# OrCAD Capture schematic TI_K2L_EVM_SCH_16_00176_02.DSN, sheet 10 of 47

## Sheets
10 PAGE37 : K2L_XDS200_1: size C; title: XDS200 / AM1802, flash, USB connector for Emulator
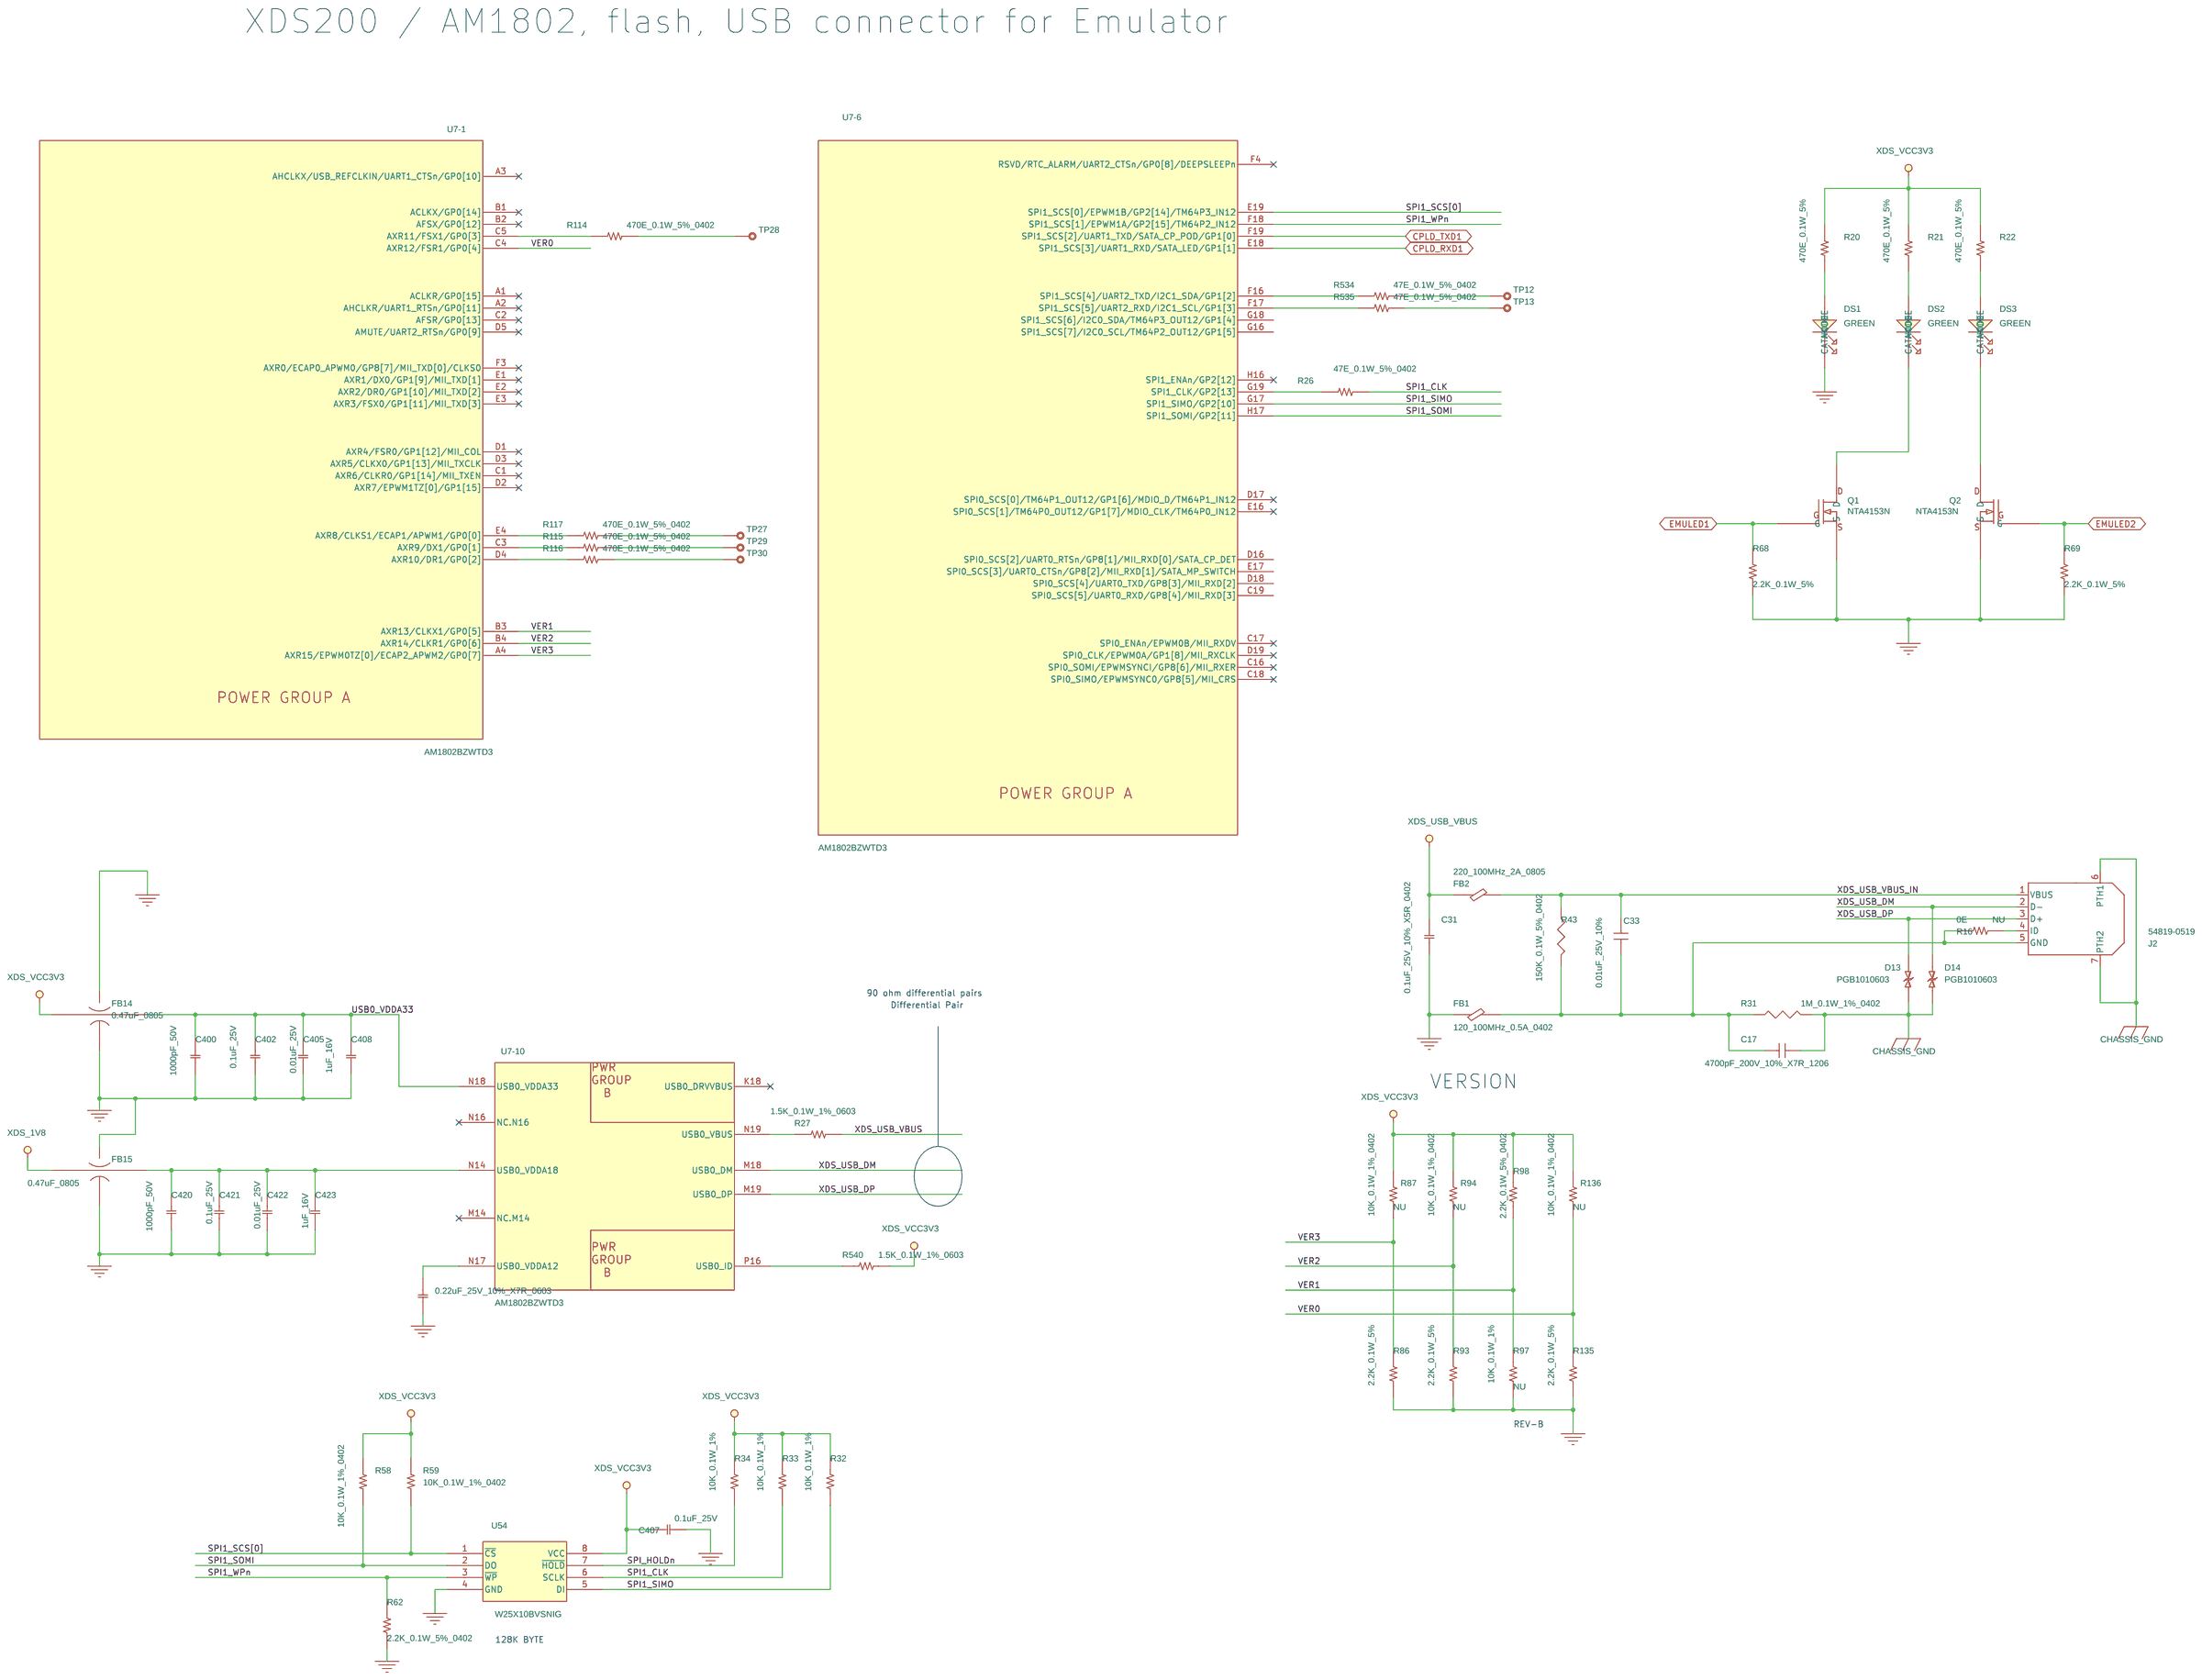
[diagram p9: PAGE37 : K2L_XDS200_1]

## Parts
sheet PAGE37 : K2L_XDS200_1
C17  4700pF_200V_10%_X7R_1206  [C1206-40X70]
C31  0.1uF_25V_10%_X5R_0402  [C0402]
C33  0.01uF_25V_10%  [C0402]
C400  1000pF_50V  [C0402]
C402  0.1uF_25V  [C0402]
C405  0.01uF_25V  [C0402]
C407  0.1uF_25V  [C0402]
C408  1uF_16V  [C0402]
C409  0.22uF_25V_10%_X7R_0603  [C0603]
C420  1000pF_50V  [C0402]
C421  0.1uF_25V  [C0402]
C422  0.01uF_25V  [C0402]
C423  1uF_16V  [C0402]
D13  PGB1010603  [SUP_PGB1010603MR]
D14  PGB1010603  [SUP_PGB1010603MR]
DS1  GREEN  [led603-35x45-rev]
DS2  GREEN  [led603-35x45-rev]
DS3  GREEN  [led603-35x45-rev]
FB1  120_100MHz_0.5A_0402  [L0402]
FB2  220_100MHz_2A_0805  [L0805]
FB14  0.47uF_0805  [FIL_NFM21PC]
FB15  0.47uF_0805  [FIL_NFM21PC]
J2  54819-0519  [MOL54819-0519]
Q1  NTA4153N  [SOT416_3P]
Q2  NTA4153N  [SOT416_3P]
R16  0E  [R0402]
R20  470E_0.1W_5%  [R0402]
R21  470E_0.1W_5%  [R0402]
R22  470E_0.1W_5%  [R0402]
R26  47E_0.1W_5%_0402  [R0402]
R27  1.5K_0.1W_1%_0603  [R0603]
R31  1M_0.1W_1%_0402  [R0402]
R32  10K_0.1W_1%  [R0402]
R33  10K_0.1W_1%  [R0402]
R34  10K_0.1W_1%  [R0402]
R43  150K_0.1W_5%_0402  [R0402]
R58  10K_0.1W_1%_0402  [R0402]
R59  10K_0.1W_1%_0402  [R0402]
R62  2.2K_0.1W_5%_0402  [R0402]
R68  2.2K_0.1W_5%  [R0402]
R69  2.2K_0.1W_5%  [R0402]
R86  2.2K_0.1W_5%  [R0402]
R87  10K_0.1W_1%_0402  [R0402]
R93  2.2K_0.1W_5%  [R0402]
R94  10K_0.1W_1%_0402  [R0402]
R97  10K_0.1W_1%  [R0402]
R98  2.2K_0.1W_5%_0402  [R0402]
R114  470E_0.1W_5%_0402  [R0402]
R115  470E_0.1W_5%_0402  [R0402]
R116  470E_0.1W_5%_0402  [R0402]
R117  470E_0.1W_5%_0402  [R0402]
R135  2.2K_0.1W_5%  [R0402]
R136  10K_0.1W_1%_0402  [R0402]
R534  47E_0.1W_5%_0402  [R0402]
R535  47E_0.1W_5%_0402  [R0402]
R540  1.5K_0.1W_1%_0603  [R0603]
TP12  Test Point  [TP-S40]
TP13  Test Point  [TP-S40]
TP27  TP  [TP-S40]
TP28  TP  [TP-S40]
TP29  TP  [TP-S40]
TP30  TP  [TP-S40]
U54  W25X10BVSNIG  [SOIC127P600_8]
sheet PAGE39 : K2L_XDS200_3
U7  AM1802BZWTD3  [BGA80P_16X16_361]  (sections -1,-10,-11,-12,-13,-14,-15,-16,-2,-3,-4,-5,-6,-7,-8,-9)

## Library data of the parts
C17 = Cap_100nF_Cermc_16V_10%_603_6: CAP CER 4700PF 200V 10% X7R 1206; Distributor_name: DIGIKEY; Distributor_part_number: 399-8198-1-ND; Manufacture: Kemet; Manufacture Part Number: C1206C472K2RACTU; Manufacture(English): Kemet; Manufacture_Part_Number: ECJ-1VB1C104K; Manufacturer: Kemet; Manufacturer_Part_No: C1206C472K2RACTU; Mfr_name: Kemet; Mfr_part_number: C1206C472K2RACTU; Part #: 103604-1472R; Vendor: DIGIKEY; Vendor_Part_No: 399-8198-1-ND
C31 C407 = 11_C_0: CAP CER 0.1UF 25V 10% X5R 0402; Alt Mfg: Taiyo Yuden; Distributor_name: DIGIKEY; Distributor_part_number: 445-4964-1-ND; EIC Part#: 03_00470_02; Manufacture: TDK Corporation; Manufacture Part Number: C1005X5R1E104K050BC; Manufacture(English): TDK Corporation; Manufacture_Part_Number: GRM155R61E104KA87D; Manufacturer: TDK Corporation; Manufacturer_Part_No: C1005X5R1E104K050BC; Mfg: Murata Electronics North America; Mfg Part#: 03_00470_02; Mfr_name: TDK Corporation; Mfr_part_number: C1005X5R1E104K050BC; Oper. Temp. Range: -55°C ~ 85°C; Package: 0402; Price @ 1: 0.10000; Price @ 1K: 0.00960; ProcessType: SMT; RoHS: Yes; Tolerance: 10%; Vendor: DIGIKEY; Vendor Part#: 445-4964-1-ND; Vendor_Part_No: 445-4964-1-ND; eI Part#: 03_00470_02
C33 = Cap_100nF_Cermc_16V_10%_603_6: CAP CER 10000PF 25V 10% X7R 0402; Distributor_name: DIGIKEY; Distributor_part_number: 445-1260-1-ND; EIC Part#: 03_00029_04; Manufacture: TDK Corporation; Manufacture Part Number: C1005X7R1E103K; Manufacture(English): TDK Corporation; Manufacture_Part_Number: C1005X7R1E103K; Manufacturer: TDK Corporation; Manufacturer_Part_No: C1005X7R1E103K; Mfg: TDK Corporation; Mfg Part#: 03_00455_02; Mfr_name: TDK Corporation; Mfr_part_number: C1005X7R1E103K; Price @ 1: 0.10000; Price @ 10K: 0.00460; Price @ 1K: 0.00600; ProcessType: SMT; Vendor: DIGIKEY; Vendor_Part_No: 445-1260-1-ND; eI Part#: 03_00029_04
C400 C420 = 11_C_0: CAP CER 1000PF 50V 10% X7R 0402; Advansus_Part_Number: 11G232110214030; Distributor_name: DIGIKEY; Distributor_part_number: 1276-1493-1-ND; EIC Part#: 03_00591_01; Manufacture: Samsung; Manufacture Part Number: CL05B102KB5NFNC; Manufacture(English): Samsung; Manufacture_Part_Number: CL05B102KB5NFNC; Manufacturer: Samsung; Manufacturer_Part_No: CL05B102KB5NFNC; Mfg: Samsung; Mfg Part#: CL05B102KB5NFNC; Mfr_name: Samsung; Mfr_part_number: CL05B102KB5NFNC; Oper. Temp. Range: -55C to 85C; Package: 0402; Price @ 1: 0.10000; Price @ 10K: 0.00260; Price @ 1K: 0.00372; ProcessType: SMT; RoHS: Yes; Tolerance: 10%; Vendor: DIGIKEY; Vendor Part#: 1276-1493-1-ND; Vendor_Part_No: 1276-1493-1-ND; Voltage: 50V; eI Part#: 03_00591_01
C402 C421 = 11_C_12: CAP CER 0.1UF 25V 10% X5R 0402; Alt Mfg: Taiyo Yuden; Distributor_name: DIGIKEY; Distributor_part_number: 445-4964-1-ND; EIC Part#: 03_00470_02; Manufacture: TDK Corporation; Manufacture Part Number: C1005X5R1E104K050BC; Manufacture(English): TDK Corporation; Manufacture_Part_Number: GRM155R61E104KA87D; Manufacturer: TDK Corporation; Manufacturer_Part_No: C1005X5R1E104K050BC; Mfg: Murata Electronics North America; Mfg Part#: 03_00470_02; Mfr_name: TDK Corporation; Mfr_part_number: C1005X5R1E104K050BC; Oper. Temp. Range: -55°C ~ 85°C; Package: 0402; Price @ 1: 0.10000; Price @ 1K: 0.00960; ProcessType: SMT; RoHS: Yes; Tolerance: 10%; Vendor: DIGIKEY; Vendor Part#: 445-4964-1-ND; Vendor_Part_No: 445-4964-1-ND; eI Part#: 03_00470_02
C405 C422 = 11_C_0: CAP CER 10000PF 25V 10% X7R 0402; Alt Mfg: Murata; Alt Mfg Part#: GRM155R71C103KA01D; Distributor_name: DIGIKEY; Distributor_part_number: 445-1260-1-ND; EIC Part#: 03_00029_04; Manufacture: TDK Corporation; Manufacture Part Number: C1005X7R1E103K; Manufacture(English): TDK Corporation; Manufacture_Part_Number: C1005X7R1E103K; Manufacturer: TDK Corporation; Manufacturer_Part_No: C1005X7R1E103K; Mfg: TDK Corporation; Mfg Part#: 03_00029_04; Mfr_name: TDK Corporation; Mfr_part_number: C1005X7R1E103K; Oper. Temp. Range: -55C to 125C; Package: 0402; Price @ 1: 0.10000; Price @ 10K: 0.00420; Price @ 1K: 0.00600; ProcessType: SMT; RoHS: Yes; Tolerance: 10%; Vendor: DIGIKEY; Vendor Part#: PCC103BQCT-ND; Vendor_Part_No: 445-1260-1-ND; Voltage: 16V; eI Part#: 03_00029_04
C408 C423 = 11_C_12: CAP CER 1UF 16V 10% X5R 0402; Characteristic: <Characteristic>; Distributor_name: DIGIKEY; Distributor_part_number: 445-4978-1-ND; EIC Part#: 03_00355_04; Manufacture: TDK Corporation; Manufacture Part Number: C1005X5R1C105K050BC; Manufacture(English): TDK Corporation; Manufacture_Part_Number: C1005X5R1C105K050BC; Manufacturer: TDK Corporation; Manufacturer_Part_No: C1005X5R1C105K050BC; Mfg: TDK Corporation; Mfg Part#: C1005X5R1C105K050BC; Mfr_name: TDK Corporation; Mfr_part_number: C1005X5R1C105K050BC; Oper. Temp. Range: -55C to 85C; Package: 0402; Price @ 1: 0.12000; Price @ 10K: 0.01600; Price @ 1K: 0.02200; ProcessType: SMT; RoHS: Yes; Tolerance: 10%; Vendor: DIGIKEY; Vendor Part#: 445-4978-1-ND; Vendor_Part_No: 445-4978-1-ND; Voltage: 6.3V; eI Part#: 03_00355_04
C409 = 11_C_0: CAP CER 0.22UF 25V 10% X7R 0603; Distributor_name: DIGIKEY; Distributor_part_number: 490-3290-1-ND; EIC Part#: TBD; Manufacture: Murata; Manufacture Part Number: GRM188R71E224KA88D; Manufacture(English): Murata; Manufacture_Part_Number: GRM188R71E224KA88D; Manufacturer: Murata; Manufacturer_Part_No: GRM188R71E224KA88D; Mfg Part#: TBD; Mfr_name: Murata; Mfr_part_number: GRM188R71E224KA88D; Oper. Temp. Range: -55C ~ 125C; Package: 0603; ProcessType: SMT; RoHS: Yes; Tolerance: 10%; Vendor: DIGIKEY; Vendor Part#: 490-3290-1-ND; Vendor_Part_No: 490-3290-1-ND; eI Part#: TBD
D13 D14 = 130_ESD_D0603_0: SUPPRESSOR ESD 24VDC 0603 SMD; Distributor_name: DIGIKEY; Distributor_part_number: F2594CT-ND; EIC Part#: TBD; Manufacture: Littelfuse Inc; Manufacture Part Number: PGB1010603MR; Manufacture(English): Littelfuse Inc; Manufacture_Part_Number: PGB1010603MR; Manufacturer: Littelfuse Inc; Manufacturer_Part_No: PGB1010603MR; Mfg Part#: TBD; Mfr_name: Littelfuse Inc; Mfr_part_number: PGB1010603MR; Package: 0603; ProcessType: SMT; RoHS: Yes; Vendor: DIGIKEY; Vendor Part#: F2594CT-ND; Vendor_Part_No: F2594CT-ND; eI Part#: TBD
DS1-DS3 = SMF-2432GC_1: LED 570NM GRN WHT/DIFF 0603 SMD; Distributor_name: DIGIKEY; Distributor_part_number: 511-1308-1-ND; EIC Part#: 06_00364_01; Manufacture: Rohm Semiconductor; Manufacture Part Number: SML-510MWT86; Manufacture(English): Rohm Semiconductor; Manufacturer: Rohm Semiconductor; Manufacturer_Part_No: SML-510MWT86; Mfg Part#: 06_00364_01; Mfr_name: Rohm Semiconductor; Mfr_part_number: SML-510MWT86; Part #: 103557-0001R; Vendor: DIGIKEY; Vendor_Part_No: 511-1308-1-ND; eI Part#: 06_00364_01
FB1 = 1212_BEAD_0: FERRITE CHIP 120 OHM 500MA 0402; Distributor_name: DIGIKEY; Distributor_part_number: 490-1005-1-ND; EIC Part#: 04_00075_01; Manufacture: Murata; Manufacture Part Number: BLM15AG121SN1D; Manufacture(English): Murata; Manufacture_Part_Number: BLM15AG121SN1D; Manufacturer: Murata; Manufacturer_Part_No: BLM15AG121SN1D; Mfg: Murata Electronics North America; Mfg Part#: BLM15AG121SN1D; Mfr_name: Murata; Mfr_part_number: BLM15AG121SN1D; Oper. Temp. Range: -55C to 85C; Package: 0402; Price @ 1: 0.10000; Price @ 10K: 0.02016; Price @ 1K: 0.02905; ProcessType: SMT; RoHS: Yes; Tolerance: 25%; Vendor: DIGIKEY; Vendor Part#: 490-1005-1-ND; Vendor_Part_No: 490-1005-1-ND; eI Part#: 04_00075_01
FB2 = 1212_BEAD_0: FERRITE CHIP 220 OHM 0805; Distributor_name: DIGIKEY; Distributor_part_number: 490-1054-1-ND; EIC Part#: 04_00016_01; Manufacture: Murata; Manufacture Part Number: BLM21PG221SN1D; Manufacture(English): Murata; Manufacture_Part_Number: BLM21PG221SN1D; Manufacturer: Murata; Manufacturer_Part_No: BLM21PG221SN1D; Mfg: Murata Electronics North America; Mfg Part#: 04_00016_01; Mfr_name: Murata; Mfr_part_number: BLM21PG221SN1D; Oper. Temp. Range: -55C to 85C; Package: 0805; Price @ 1: 0.11000; Price @ 10K: 0.02368; Price @ 1K: 0.03093; ProcessType: SMT; RoHS: Yes; Vendor: DIGIKEY; Vendor Part#: 490-1054-1-ND; Vendor_Part_No: 490-1054-1-ND; eI Part#: 04_00016_01
FB14 FB15 = NFM_3: FILTER LC HIGH FREQ .47UF 0805; Distributor_name: DIGIKEY; Distributor_part_number: 490-2537-1-ND; EIC Part#: 04_00213_01; Manufacture: Murata; Manufacture Part Number: NFM21PC474R1C3D; Manufacture(English): Murata; Manufacture_Part_Number: NFM21PC474R1C3D; Manufacturer: Murata; Manufacturer_Part_No: NFM21PC474R1C3D; Mfg Part#: 04_00213_01; Mfr_name: Murata; Mfr_part_number: NFM21PC474R1C3D; Part #: 102569-1470R; RoHS: Yes; Tolerance: 20%; Vendor: DIGIKEY; Vendor Part#: 490-2537-1-ND; Vendor_Part_No: 490-2537-1-ND; eI Part#: 04_00213_01
J2 = 678038020_0: MINI USB TYPE B CONNECTOR, RCPT 5POS THD; Distributor_name: ELEMENT14; Distributor_part_number: 2133828; EIC Part#: 09_00954_01; Manufacture: Molex Inc; Manufacture(English): Molex Inc; Manufacturer: Molex Inc; Mfg: Molex Inc; Mfg Part#: 09_00954_01; Mfr_name: Molex Inc; Price @ 1: 2.40000; Price @ 10K: 1.77000; Price @ 1K: 1.77000; Vendor: ELEMENT14; Vendor_Part_No: 2133828; eI Part#: 09_00954_01
Q1 Q2 = NTA4153N: MOSFET N-CH 20V 915MA SOT-416; Distributor_name: DIGIKEY; Distributor_part_number: NTA4153NT1GOSCT-ND; EIC Part#: 07_00042_01; Manufacture: ON Semiconductor; Manufacture Part Number: NTA4153NT1G; Manufacture(English): ON Semiconductor; Manufacture_Part_Number: NTA4153NT1G; Manufacturer: ON Semiconductor; Manufacturer_Part_No: NTA4153NT1G; Mfg Part#: 07_00042_01; Mfr_name: ON Semiconductor; Mfr_part_number: NTA4153NT1G; Package: SC-75; Part #: 102437-0001R; RoHS: Yes; Vendor: DIGIKEY; Vendor Part#: NTA4153NT1GOSCT-ND; Vendor_Part_No: NTA4153NT1GOSCT-ND; eI Part#: 07_00042_01
R16 = 10_R_0: RES 0.0 OHM 1/10W JUMP 0402 SMD; Alt Mfg: Yageo; Distributor_name: DIGIKEY; Distributor_part_number: P0.0JCT-ND; EIC Part#: 02_00019_01; Manufacture: Panasonic - ECG; Manufacture Part Number: ERJ-2GE0R00X; Manufacture(English): Panasonic - ECG; Manufacture_Part_Number: ERJ-2GE0R00X; Manufacturer: Panasonic - ECG; Manufacturer_Part_No: ERJ-2GE0R00X; Mfg: Panasonic - ECG; Mfg Part#: 02_00019_01; Mfr_name: Panasonic - ECG; Mfr_part_number: ERJ-2GE0R00X; Mounting Status: NU; Oper. Temp. Range: -55C to 125C; Package: 0402; ProcessType: SMT; Remark: Alt part is 1/16W; RoHS: Yes; Tolerance: 5%; Vendor: DIGIKEY; Vendor Part#: P0.0JCT-ND; Vendor_Part_No: P0.0JCT-ND; eI Part#: 02_00019_01
R20-R22 R116 = 10_R_0: RES 470 OHM 1/10W 5% 0402 SMD; Alt Mfg: Yageo; Alt Mfg Part#: RC0402JR-070RL; Distributor_name: DIGIKEY; Distributor_part_number: P470JCT-ND; EIC Part#: 02_00483_01; Manufacture: Panasonic - ECG; Manufacture Part Number: ERJ-2GEJ471X; Manufacture(English): Panasonic - ECG; Manufacture_Part_Number: ERJ-2GEJ471X; Manufacturer: Panasonic - ECG; Manufacturer_Part_No: ERJ-2GEJ471X; Mfg Part#: 02_00483_01; Mfr_name: Panasonic - ECG; Mfr_part_number: ERJ-2GEJ471X; Oper. Temp. Range: -55C to 125C; Package: 0402; ProcessType: SMT; Remark: Alt part is 1/16W; RoHS: Yes; Tolerance: 5%; Vendor: DIGIKEY; Vendor Part#: P470JDKR-ND; Vendor_Part_No: P470JCT-ND; eI Part#: 02_00045_01
R26 R535 = 10_R_0: RES 47 OHM 1/10W 5% 0402 SMD; Alt Mfg: Yageo; Alt Mfg Part#: RC0402JR-070RL; Distributor_name: DIGIKEY; Distributor_part_number: P47JCT-ND; EIC Part#: 02_00558_01; Manufacture: Panasonic - ECG; Manufacture Part Number: ERJ-2GEJ470X; Manufacture(English): Panasonic - ECG; Manufacture_Part_Number: ERJ-2GEJ470X; Manufacturer: Panasonic - ECG; Manufacturer_Part_No: ERJ-2GEJ470X; Mfg Part#: 02_00558_01; Mfr_name: Panasonic - ECG; Mfr_part_number: ERJ-2GEJ470X; Oper. Temp. Range: -55C to 125C; Package: 0402; ProcessType: SMT; Remark: Alt part is 1/16W; RoHS: Yes; Tolerance: 5%; Vendor: DIGIKEY; Vendor Part#: P47JCT-ND; Vendor_Part_No: P47JCT-ND; eI Part#: 02_00027_01
R27 R540 = 10_R_0: RES 1.50K OHM 1/10W 1% 0603 SMD; Distributor_name: DIGIKEY; Distributor_part_number: P1.50KHCT-ND; EIC Part#: 02_00122_02; Manufacture: Panasonic - ECG; Manufacture Part Number: ERJ-3EKF1501V; Manufacture(English): Panasonic - ECG; Manufacture_Part_Number: ERJ-3EKF1501V; Manufacturer: Panasonic - ECG; Manufacturer_Part_No: ERJ-3EKF1501V; Mfg Part#: 02_00122_02; Mfr_name: Panasonic - ECG; Mfr_part_number: ERJ-3EKF1501V; Oper. Temp. Range: -55C to 125C; Package: 0603; ProcessType: SMT; RoHS: Yes; Tolerance: 1%; Vendor: DIGIKEY; Vendor Part#: P1.50KHCT-ND; Vendor_Part_No: P1.50KHCT-ND; eI Part#: 02_00027_01
R31 = R: RES 1.00M OHM 1/16W 1% 0402 SMD; Distributor_name: DIGIKEY; Distributor_part_number: 311-1.00MLRCT-ND; EIC Part#: 02_00057_02; Manufacture: Yageo; Manufacture Part Number: RC0402FR-071ML; Manufacture(English): Yageo; Manufacturer: Yageo; Manufacturer_Part_No: RC0402FR-071ML; Mfg Part#: 02_00095_01; Mfr_name: Yageo; Mfr_part_number: RC0402FR-071ML; Vendor: DIGIKEY; Vendor_Part_No: 311-1.00MLRCT-ND; eI Part#: 02_00057_02
R32-R34 R58 R59 = 10_R_0: RES 10K OHM 1/10W 1% 0402 SMD; Alt Mfg: Yageo; Alt Mfg Part#: RC0402FR-0710KL; Distributor_name: DIGIKEY; Distributor_part_number: P10.0KLCT-ND; EIC Part#: 02_00027_01; Manufacture: Panasonic - ECG; Manufacture Part Number: ERJ-2RKF1002X; Manufacture(English): Panasonic - ECG; Manufacture_Part_Number: ERJ-2RKF1002X; Manufacturer: Panasonic - ECG; Manufacturer_Part_No: ERJ-2RKF1002X; Mfg Part#: 02_00027_01; Mfr_name: Panasonic - ECG; Mfr_part_number: ERJ-2RKF1002X; Oper. Temp. Range: -55C ~ 125C; Package: 0402; Price @ 1: 0.10000; Price @ 10K: 0.00347; Price @ 1K: 0.00672; ProcessType: SMT; Remark: Alt part is 1/16W; RoHS: Yes; Tolerance: 1%; Vendor: DIGIKEY; Vendor Part#: P10.0KLCT-ND; Vendor_Part_No: P10.0KLCT-ND; eI Part#: 02_00027_01
R43 = R: RES 150K OHM 1/10W 5% 0402 SMD; Distributor_name: DIGIKEY; Distributor_part_number: P150KJCT-ND; EIC Part#: 02_00366_02; Manufacture: Panasonic - ECG; Manufacture Part Number: ERJ-2GEJ154X; Manufacture(English): Panasonic - ECG; Manufacturer: Panasonic - ECG; Manufacturer_Part_No: ERJ-2GEJ154X; Mfg Part#: 02_00366_02; Mfr_name: Panasonic - ECG; Mfr_part_number: ERJ-2GEJ154X; Part #: 101370-1504R; Part Number: ECJ-1VB1C104K; Type: X7R Ceramic Chip Cap; Vendor: DIGIKEY; Vendor_Part_No: P150KJCT-ND; eI Part#: 02_00045_01
R62 = 10_R_0: RES 2.2K OHM 1/10W 5% 0402 SMD; Alt Mfg: Yageo; Alt Mfg Part#: RC0402JR-072K2L; Distributor_name: DIGIKEY; Distributor_part_number: P2.2KJCT-ND; EIC Part#: 02_00024_01; Manufacture: Panasonic - ECG; Manufacture Part Number: ERJ-2GEJ222X; Manufacture(English): Panasonic - ECG; Manufacture_Part_Number: ERJ-2GEJ222X; Manufacturer: Panasonic - ECG; Manufacturer_Part_No: ERJ-2GEJ222X; Mfg Part#: 02_00024_01; Mfr_name: Panasonic - ECG; Mfr_part_number: ERJ-2GEJ222X; Oper. Temp. Range: -55C to 125C; Package: 0402; ProcessType: SMT; Remark: Alt part is 1/16W; RoHS: Yes; Specifications: RES 2.2K OHM 1/10W 5% 0402 SMD; Tolerance: 5%; Vendor: DIGIKEY; Vendor Part#: P2.2KJCT-ND; Vendor_Part_No: P2.2KJCT-ND; eI Part#: 02_00233_01
R68 R69 R135 = 10_R_0: RES 2.2K OHM 1/10W 5% 0402 SMD; Alt Mfg: Yageo; Alt Mfg Part#: RC0402JR-072K2L; Distributor_name: DIGIKEY; Distributor_part_number: P2.2KJCT-ND; EIC Part#: 02_00024_01; Manufacture: Panasonic - ECG; Manufacture Part Number: ERJ-2GEJ222X; Manufacture(English): Panasonic - ECG; Manufacture_Part_Number: ERJ-2GEJ222X; Manufacturer: Panasonic - ECG; Manufacturer_Part_No: ERJ-2GEJ222X; Mfg Part#: 02_00024_01; Mfr_name: Panasonic - ECG; Mfr_part_number: ERJ-2GEJ222X; Oper. Temp. Range: -55C to 125C; Package: 0402; ProcessType: SMT; Remark: Alt part is 1/16W; RoHS: Yes; Specifications: RES 2.2K OHM 1/10W 5% 0402 SMD; Tolerance: 5%; Vendor: DIGIKEY; Vendor Part#: P2.2KJCT-ND; Vendor_Part_No: P2.2KJCT-ND; eI Part#: 02_00045_01
R86 R93 = 10_R_0: RES 2.2K OHM 1/10W 5% 0402 SMD; Alt Mfg: Yageo; Alt Mfg Part#: RC0402JR-072K2L; Distributor_name: DIGIKEY; Distributor_part_number: P2.2KJCT-ND; EIC Part#: 02_00024_01; Manufacture: Panasonic - ECG; Manufacture Part Number: ERJ-2GEJ222X; Manufacture(English): Panasonic - ECG; Manufacture_Part_Number: ERJ-2GEJ222X; Manufacturer: Panasonic - ECG; Manufacturer_Part_No: ERJ-2GEJ222X; Mfg Part#: 02_00024_01; Mfr_name: Panasonic - ECG; Mfr_part_number: ERJ-2GEJ222X; Oper. Temp. Range: -55C to 125C; Package: 0402; ProcessType: SMT; Remark: Alt part is 1/16W; RoHS: Yes; Specifications: RES 2.2K OHM 1/10W 5% 0402 SMD; Tolerance: 5%; Vendor: DIGIKEY; Vendor Part#: P2.2KJCT-ND; Vendor_Part_No: P2.2KJCT-ND; eI Part#: 02_00027_01
R87 R94 R97 R136 = 10_R_0: RES 10K OHM 1/10W 1% 0402 SMD; Alt Mfg: Yageo; Alt Mfg Part#: RC0402FR-0710KL; Distributor_name: DIGIKEY; Distributor_part_number: P10.0KLCT-ND; EIC Part#: 02_00027_01; Manufacture: Panasonic - ECG; Manufacture Part Number: ERJ-2RKF1002X; Manufacture(English): Panasonic - ECG; Manufacture_Part_Number: ERJ-2RKF1002X; Manufacturer: Panasonic - ECG; Manufacturer_Part_No: ERJ-2RKF1002X; Mfg Part#: 02_00027_01; Mfr_name: Panasonic - ECG; Mfr_part_number: ERJ-2RKF1002X; Mounting: NU; Mounting Status: NU; Mounting_Status: NU; Oper. Temp. Range: -55C ~ 125C; Package: 0402; Price @ 1: 0.10000; Price @ 10K: 0.00347; Price @ 1K: 0.00672; ProcessType: SMT; Remark: Alt part is 1/16W; RoHS: Yes; Tolerance: 1%; Vendor: DIGIKEY; Vendor Part#: P10.0KLCT-ND; Vendor_Part_No: P10.0KLCT-ND; eI Part#: 02_00027_01
R98 = 10_R_0: RES 2.2K OHM 1/10W 5% 0402 SMD; Alt Mfg: Yageo; Alt Mfg Part#: RC0402JR-072K2L; Distributor_name: DIGIKEY; Distributor_part_number: P2.2KJCT-ND; EIC Part#: 02_00024_01; Manufacture: Panasonic - ECG; Manufacture Part Number: ERJ-2GEJ222X; Manufacture(English): Panasonic - ECG; Manufacture_Part_Number: ERJ-2GEJ222X; Manufacturer: Panasonic - ECG; Manufacturer_Part_No: ERJ-2GEJ222X; Mfg Part#: 02_00024_01; Mfr_name: Panasonic - ECG; Mfr_part_number: ERJ-2GEJ222X; Oper. Temp. Range: -55C to 125C; Package: 0402; ProcessType: SMT; Remark: Alt part is 1/16W; RoHS: Yes; Specifications: RES 2.2K OHM 1/10W 5% 0402 SMD; Tolerance: 5%; Vendor: DIGIKEY; Vendor Part#: P2.2KJCT-ND; Vendor_Part_No: P2.2KJCT-ND; eI Part#: 02_00483_01
R114 = 10_R_0: RES 470 OHM 1/10W 5% 0402 SMD; Alt Mfg: Yageo; Alt Mfg Part#: RC0402JR-070RL; Distributor_name: DIGIKEY; Distributor_part_number: P470JCT-ND; EIC Part#: 02_00483_01; Manufacture: Panasonic - ECG; Manufacture Part Number: ERJ-2GEJ471X; Manufacture(English): Panasonic - ECG; Manufacture_Part_Number: ERJ-2GEJ471X; Manufacturer: Panasonic - ECG; Manufacturer_Part_No: ERJ-2GEJ471X; Mfg Part#: 02_00483_01; Mfr_name: Panasonic - ECG; Mfr_part_number: ERJ-2GEJ471X; Oper. Temp. Range: -55C to 125C; Package: 0402; ProcessType: SMT; Remark: Alt part is 1/16W; RoHS: Yes; Tolerance: 5%; Vendor: DIGIKEY; Vendor Part#: P470JDKR-ND; Vendor_Part_No: P470JCT-ND; eI Part#: 02_00483_01
R115 R117 = 10_R_0: RES 470 OHM 1/10W 5% 0402 SMD; Alt Mfg: Yageo; Alt Mfg Part#: RC0402JR-070RL; Distributor_name: DIGIKEY; Distributor_part_number: P470JCT-ND; EIC Part#: 02_00483_01; Manufacture: Panasonic - ECG; Manufacture Part Number: ERJ-2GEJ471X; Manufacture(English): Panasonic - ECG; Manufacture_Part_Number: ERJ-2GEJ471X; Manufacturer: Panasonic - ECG; Manufacturer_Part_No: ERJ-2GEJ471X; Mfg Part#: 02_00483_01; Mfr_name: Panasonic - ECG; Mfr_part_number: ERJ-2GEJ471X; Oper. Temp. Range: -55C to 125C; Package: 0402; ProcessType: SMT; Remark: Alt part is 1/16W; RoHS: Yes; Tolerance: 5%; Vendor: DIGIKEY; Vendor Part#: P470JDKR-ND; Vendor_Part_No: P470JCT-ND; eI Part#: 02_00027_01
R534 = 10_R_0: RES 47 OHM 1/10W 5% 0402 SMD; Alt Mfg: Yageo; Alt Mfg Part#: RC0402JR-070RL; Distributor_name: DIGIKEY; Distributor_part_number: P47JCT-ND; EIC Part#: 02_00558_01; Manufacture: Panasonic - ECG; Manufacture Part Number: ERJ-2GEJ470X; Manufacture(English): Panasonic - ECG; Manufacture_Part_Number: ERJ-2GEJ470X; Manufacturer: Panasonic - ECG; Manufacturer_Part_No: ERJ-2GEJ470X; Mfg Part#: 02_00558_01; Mfr_name: Panasonic - ECG; Mfr_part_number: ERJ-2GEJ470X; Oper. Temp. Range: -55C to 125C; Package: 0402; ProcessType: SMT; Remark: Alt part is 1/16W; RoHS: Yes; Tolerance: 5%; Vendor: DIGIKEY; Vendor Part#: P47JCT-ND; Vendor_Part_No: P47JCT-ND; eI Part#: 02_00233_01
TP12 TP13 = 00_TP-S40_0: TEST PAD TP-S40; Distributor_name: NA; Distributor_part_number: NA; EIC Part#: NA; Manufacture: NA; Manufacture Part Number: NA; Manufacture(English): NA; Manufacturer: NA; Manufacturer_Part_No: NA; Mfg: NA; Mfg Part#: NA; Mfr_name: NA; Mfr_part_number: NA; Oper. Temp. Range: NA; Package: NA; ProcessType: SMT; RoHS: Yes; Vendor: NA; Vendor Part#: NA; Vendor_Part_No: NA; eI Part#: NA
TP27 TP29 TP30 = 00_TP-S40_0: TEST PAD TP; Distributor_name: NA; Distributor_part_number: NA; EIC Part#: NA; Manufacture: NA; Manufacture Part Number: NA; Manufacture(English): NA; Manufacture_Part_Number: NA; Manufacturer: NA; Manufacturer_Part_No: NA; Mfg: NA; Mfg Part#: NA; Mfr_name: NA; Mfr_part_number: NA; Oper. Temp. Range: --NA--; Package: --NA--; Price @ 1: NA; Price @ 10K: NA; Price @ 1K: NA; ProcessType: SMT; RoHS: Yes; Vendor: NA; Vendor Part#: --NA--; Vendor_Part_No: NA; eI Part#: NA
TP28 = 00_TP-S40_0: TEST PAD TP; Distributor_name: NA; Distributor_part_number: NA; EIC Part#: NA; Manufacture: NA; Manufacture Part Number: NA; Manufacture(English): NA; Manufacture_Part_Number: NA; Manufacturer: NA; Manufacturer_Part_No: NA; Mfg: NA; Mfg Part#: NA; Mfr_name: NA; Mfr_part_number: NA; Oper. Temp. Range: --NA--; Package: --NA--; Price @ 1: NA; Price @ 10K: NA; Price @ 1K: NA; ProcessType: SMT; RoHS: Yes; Vendor: NA; Vendor Part#: --NA--; Vendor_Part_No: NA; eI Part#: 01_01117_01
U54 = SPI_EEPROM_2: IC FLASH 1MBIT 104MHZ 8SOIC; Alternate_Mfr: ISSI; Alternate_Partno: IS25CD010-JNLE; Distributor_name: DIGIKEY; Distributor_part_number: W25X10BVSNIG-ND; EIC Part#: 01_01136_01; Manufacture: Winbond Electronics; Manufacture(English): Winbond Electronics; Manufacturer: Winbond Electronics; Mfg: Winbond Electronics; Mfg Part#: 01_01136_01; Mfr_name: Winbond Electronics; Oper. Temp. Range: -40°C ~ 85°C; Package: 8-SOIC; Part #: 103126-0002R; Price @ 1: TBD; Price @ 10K: TBD; Price @ 1K: TBD; RoHS: Yes; Vendor: DIGIKEY; Vendor Part#: W25X10BVSNIG-ND; Vendor_Part_No: W25X10BVSNIG-ND; eI Part#: 01_01136_01
U7 = OMAP-L138_new_5: IC ARM9 CORTEX MPU 361NFBGA; Distributor_name: DIGIKEY; Distributor_part_number: AM1802BZWTD3-ND; EIC Part#: 01_01135_01; Manufacture: TI; Manufacture(English): TI; Manufacturer: TI; Mfg: TI; Mfg Part#: 01_01135_01; Mfr_name: TI; Part #: 103922-0001R; Price @ 1: 14.51000; Price @ 1K: 14.51000; Vendor: DIGIKEY; Vendor_Part_No: AM1802BZWTD3-ND; eI Part#: 01_01147_01

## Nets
GND: C31.1 C400.1 C402.2 C405.2 C407.2 C408.2 C409.1 C420.1 C421.2 C422.2 C423.2 DS1.2(CATHODE) FB1.1 FB14.2 FB14.4 FB15.2 FB15.4 Q1.2(S) Q2.2(S) R62.2 R68.2 R69.2 R86.2 R93.2 R97.2 R135.2 U54.4(GND) ; also on sheet 1 2 3 4 5 6 8 11 12 13 14 15 16 17 18 19 20 21 22 24 25 26 27 28 29 33 34 35 36 37 40 41 42 43 45 46 47
CHASSIS_GND: C17.2 D13.1 D14.1 J2.6(PTH1) J2.7(PTH2) R31.2 ; also on sheet 8
CPLD_RXD1: U7.E18(SPI1_SCS[3]/UART1_RXD/SATA_LED/GP1[1]) ; also on sheet 42
CPLD_TXD1: U7.F19(SPI1_SCS[2]/UART1_TXD/SATA_CP_POD/GP1[0]) ; also on sheet 42
EMULED1: Q1.1(G) R68.1 ; also on sheet 15
EMULED2: Q2.1(G) R69.1 ; also on sheet 15
SPI1_CLK: R26.2 R33.1 U54.6(SCLK)
SPI1_SCS[0]: R59.1 U7.E19(SPI1_SCS[0]/EPWM1B/GP2[14]/TM64P3_IN12) U54.1(~{CS})
SPI1_SIMO: R32.1 U7.G17(SPI1_SIMO/GP2[10]) U54.5(DI)
SPI1_SOMI: R58.1 U7.H17(SPI1_SOMI/GP2[11]) U54.2(DO)
SPI1_WPn: R62.1 U7.F18(SPI1_SCS[1]/EPWM1A/GP2[15]/TM64P2_IN12) U54.3(~{WP})
SPI_HOLDn: R34.1 U54.7(~{HOLD})
USB0_VDDA33: C400.2 C402.1 C405.1 C408.1 FB14.3 U7.N18(USB0_VDDA33)
VER0: R135.1 R136.2 U7.C4(AXR12/FSR1/GP0[4])
VER1: R97.1 R98.2 U7.B3(AXR13/CLKX1/GP0[5])
VER2: R93.1 R94.2 U7.B4(AXR14/CLKR1/GP0[6])
VER3: R86.1 R87.2 U7.A4(AXR15/EPWM0TZ[0]/ECAP2_APWM2/GP0[7])
XDS_1V8: FB15.1 ; also on sheet 15 24 42
XDS_USB_DM: D14.2 J2.2(D-) U7.M18(USB0_DM)
XDS_USB_DP: D13.2 J2.3(D+) U7.M19(USB0_DP)
XDS_USB_VBUS: C31.2 FB2.2 R27.2 ; also on sheet 6 15
XDS_USB_VBUS_IN: C33.1 FB2.1 J2.1(VBUS) R43.1
XDS_VCC3V3: C407.1 FB14.1 R20.2 R21.2 R22.2 R32.2 R33.2 R34.2 R58.2 R59.2 R87.1 R94.1 R98.1 R136.1 R540.2 U54.8(VCC) ; also on sheet 14 15 24 42
N18194938: R26.1 U7.G19(SPI1_CLK/GP2[13])
N18195040: R114.2 TP28.1
N18195045: R114.1 U7.C5(AXR11/FSX1/GP0[3])
N18195079: R117.2 TP27.1
N18195081: R115.2 TP29.1
N18195083: R116.2 TP30.1
N18195085: R117.1 U7.E4(AXR8/CLKS1/ECAP1/APWM1/GP0[0])
N18195087: R115.1 U7.C3(AXR9/DX1/GP0[1])
N18195089: R116.1 U7.D4(AXR10/DR1/GP0[2])
N18195120: R534.2 TP12.1
N18195122: R535.2 TP13.1
N18195124: R535.1 U7.F17(SPI1_SCS[5]/UART2_RXD/I2C1_SCL/GP1[3])
N18195126: R534.1 U7.F16(SPI1_SCS[4]/UART2_TXD/I2C1_SDA/GP1[2])
N18195136: R540.1 U7.P16(USB0_ID)
N18195168: C409.2 U7.N17(USB0_VDDA12)
N18195184: C420.2 C421.1 C422.1 C423.1 FB15.3 U7.N14(USB0_VDDA18)
N18195369: C17.1 C33.2 FB1.2 J2.5(GND) R16.1 R31.1 R43.2
N18195441: R27.1 U7.N19(USB0_VBUS)
N18196276: DS3.1(ANODE) R22.1
N18196278: DS2.1(ANODE) R21.1
N18196327: DS3.2(CATHODE) Q2.3(D)
N18196329: DS2.2(CATHODE) Q1.3(D)
N18196351: DS1.1(ANODE) R20.1
N20300929: J2.4(ID) R16.2

Not connected (* = marked no-connect by the designer): U7 A1(ACLKR/GP0[15])* A2(AHCLKR/UART1_RTSn/GP0[11])* A3(AHCLKX/USB_REFCLKIN/UART1_CTSn/GP0[10])* B1(ACLKX/GP0[14])* B2(AFSX/GP0[12])* C1(AXR6/CLKR0/GP1[14]/MII_TXEN)* C2(AFSR/GP0[13])* C16(SPI0_SOMI/EPWMSYNCI/GP8[6]/MII_RXER)* C17(SPI0_ENAn/EPWM0B/MII_RXDV)* C18(SPI0_SIMO/EPWMSYNC0/GP8[5]/MII_CRS)* C19(SPI0_SCS[5]/UART0_RXD/GP8[4]/MII_RXD[3]) D1(AXR4/FSR0/GP1[12]/MII_COL)* D2(AXR7/EPWM1TZ[0]/GP1[15])* D3(AXR5/CLKX0/GP1[13]/MII_TXCLK)* D5(AMUTE/UART2_RTSn/GP0[9])* D16(SPI0_SCS[2]/UART0_RTSn/GP8[1]/MII_RXD[0]/SATA_CP_DET) D17(SPI0_SCS[0]/TM64P1_OUT12/GP1[6]/MDIO_D/TM64P1_IN12)* D18(SPI0_SCS[4]/UART0_TXD/GP8[3]/MII_RXD[2]) D19(SPI0_CLK/EPWM0A/GP1[8]/MII_RXCLK)* E1(AXR1/DX0/GP1[9]/MII_TXD[1])* E2(AXR2/DR0/GP1[10]/MII_TXD[2])* E3(AXR3/FSX0/GP1[11]/MII_TXD[3])* E16(SPI0_SCS[1]/TM64P0_OUT12/GP1[7]/MDIO_CLK/TM64P0_IN12)* E17(SPI0_SCS[3]/UART0_CTSn/GP8[2]/MII_RXD[1]/SATA_MP_SWITCH) F3(AXR0/ECAP0_APWM0/GP8[7]/MII_TXD[0]/CLKS0)* F4(RSVD/RTC_ALARM/UART2_CTSn/GP0[8]/DEEPSLEEPn)* G16(SPI1_SCS[7]/I2C0_SCL/TM64P2_OUT12/GP1[5]) G18(SPI1_SCS[6]/I2C0_SDA/TM64P3_OUT12/GP1[4]) H16(SPI1_ENAn/GP2[12])* K18(USB0_DRVVBUS)* M14(NC.M14)* N16(NC.N16)*

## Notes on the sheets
sheet 10
- XDS200 / AM1802, flash, USB connector for Emulator
- 90 ohm differential pairs
- Differential Pair
- VERSION
- REV-B
- 128K BYTE
